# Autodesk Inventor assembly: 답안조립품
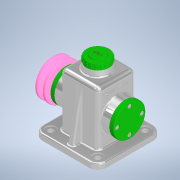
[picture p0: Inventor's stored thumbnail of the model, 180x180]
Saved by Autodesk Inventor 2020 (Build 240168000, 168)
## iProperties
Created: 2021-07
Part Number: 답안조립품
Document SubType Name: Assembly
Designer: Owner
Author: Owner
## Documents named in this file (14)
- C:\Users\Owner\Desktop\710715V1003\답안조립품.iam
- C:\Users\Owner\Desktop\710715V1003\본체.ipt
- C:\Users\Owner\Desktop\710715V1003\Ű 5 x 5 x 14.ipt
- C:\Users\Owner\Desktop\710715V1003\V-벨트풀리.ipt
- C:\Users\Owner\Desktop\710715V1003\뒤커버.ipt
- C:\Users\Owner\Desktop\710715V1003\멈춤링 15 x 1.ipt
- C:\Users\Owner\Desktop\710715V1003\베어링 15 x 35 x 11.ipt
- C:\Users\Owner\Desktop\710715V1003\볼트 M4 x 10.ipt
- C:\Users\Owner\Desktop\710715V1003\볼트 M6 x 12.ipt
- C:\Users\Owner\Desktop\710715V1003\상부캡.ipt
- C:\Users\Owner\Desktop\710715V1003\앞커버.ipt
- C:\Users\Owner\Desktop\710715V1003\오일실 15 25 7.ipt
- C:\Users\Owner\Desktop\710715V1003\와셔.ipt
- C:\Users\Owner\Desktop\710715V1003\축.ipt
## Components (2 placed, 2 different names)
1. Ű 5 x 5 x 14:1
2. V-벨트풀리:1
